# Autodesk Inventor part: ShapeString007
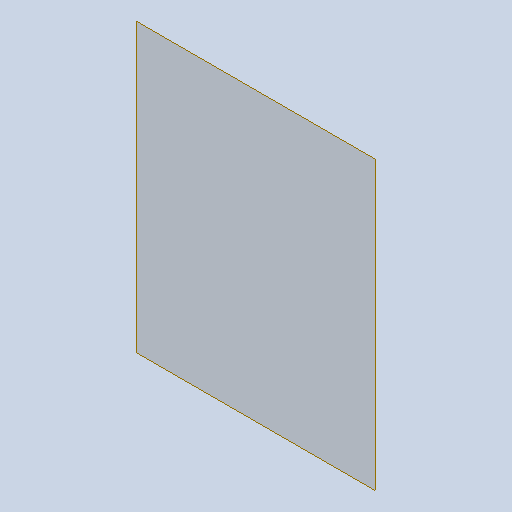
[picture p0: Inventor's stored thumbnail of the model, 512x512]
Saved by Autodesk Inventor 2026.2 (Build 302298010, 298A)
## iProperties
Created: 2026-10
Part Number: ShapeString007
Material: Générique
Document SubType Name: Modeling
Designer: mel
Density: 1 g/cm^3
Appearance: Par défaut
Author: mel
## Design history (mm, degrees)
feature "Composite1"
body "Srf1"
